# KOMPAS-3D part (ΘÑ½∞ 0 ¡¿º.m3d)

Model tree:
1. Эскиз:1
2. Операция выдавливания:1
     Расстояние 1 = 2
3. Эскиз:2
4. Вырезать элемент выдавливания:1
     Расстояние 1 = 10
5. Скругление:1
     Радиус = 1
